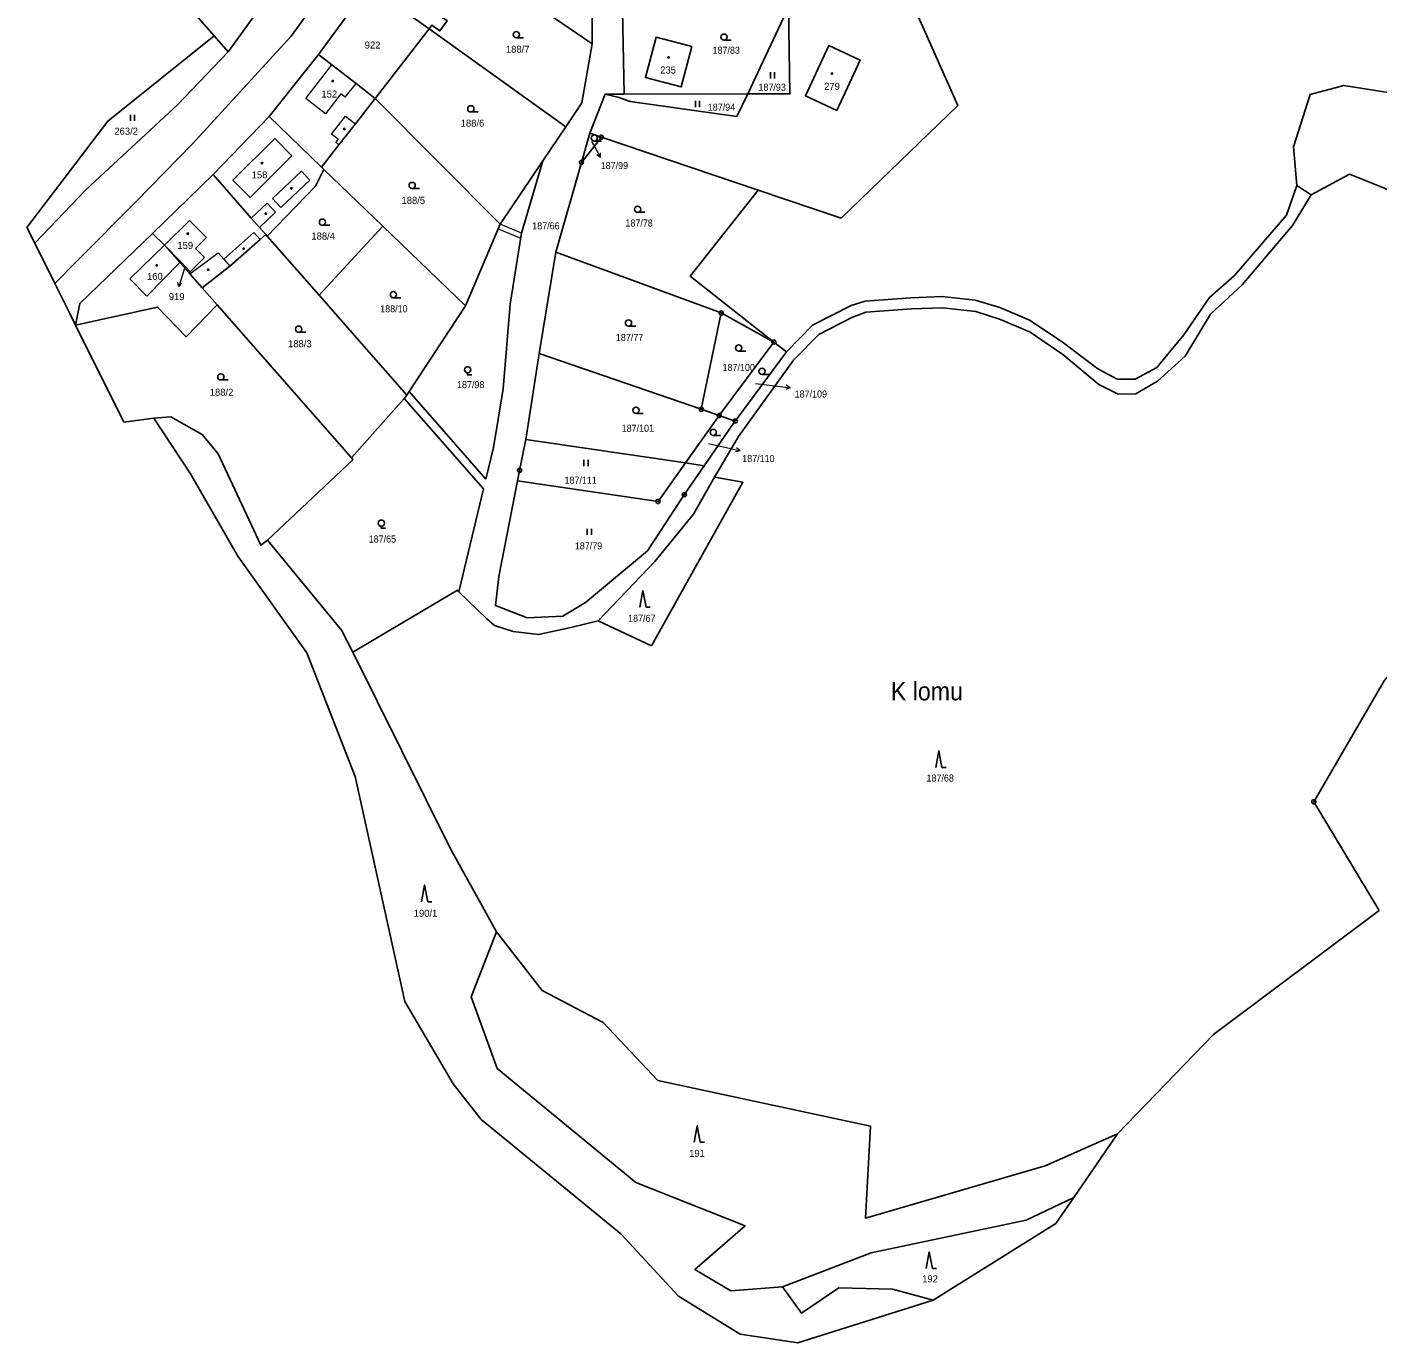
# Model space of a CAD drawing. Extents: x -754445 to -751443, y -1030748 to -1028224.
# Drawn here: x -753204.3 to -752878.6, y -1030041.6 to -1029724.1 of the extents above; entities that cross this region are included whole.
import ezdxf
from ezdxf.enums import TextEntityAlignment as Align

# ---------------------------------------------------------------- set-up
doc = ezdxf.new("R2010")
doc.units = 0
doc.header["$LTSCALE"] = 0.68
for name, color, linetype, lineweight in [('1', 7, 'Continuous', 25), ('13', 7, 'Continuous', 13), ('3', 7, 'Continuous', 25), ('4', 7, 'Continuous', 13), ('5', 7, 'Continuous', 25), ('7', 7, 'Continuous', 13), ('8', 7, 'Continuous', 25)]:
    doc.layers.add(name, color=color, linetype=linetype, lineweight=lineweight)
doc.layers.add('2', color=7, linetype='Continuous')

msp = doc.modelspace()

# ---------------------------------------------------------------- linework, layer by layer
at = {"layer": '1'}
for p, q in [((-753067.98, -1029728.16), (-753096.13, -1029708.85)), ((-753133.97, -1029730.68), (-753121.88, -1029714.12)), ((-753074.35, -1029748.12), (-753107.32, -1029724.53)), ((-753068.54, -1029749.69), (-753064.85, -1029740.24)), ((-753064.85, -1029740.24), (-753060.24, -1029740.23)), ((-753090.19, -1029771.62), (-753120.36, -1029741.3)), ((-753145.94, -1029745.69), (-753159.44, -1029759.62)), ((-753065.74, -1029750.64), (-753070.56, -1029756.75)), ((-753065.74, -1029750.64), (-753027.95, -1029763.39)), ((-753090.19, -1029771.62), (-753079.87, -1029756.31)), ((-753159.44, -1029759.62), (-753174.02, -1029773.88)), ((-753204.33, -1029772.43), (-753202.44, -1029776.23)), ((-753118.5, -1029772.12), (-753098.51, -1029791.36)), ((-753098.51, -1029791.36), (-753090.19, -1029771.62)), ((-753202.44, -1029776.23), (-753197.62, -1029785.92)), ((-753174.02, -1029773.88), (-753171.15, -1029776.66)), ((-753146.71, -1029774.13), (-753146.38, -1029774.5)), ((-753133.87, -1029788.74), (-753146.38, -1029774.5)), ((-753080.76, -1029802.85), (-753076.73, -1029778.39)), ((-753036.83, -1029793.05), (-753076.73, -1029778.39)), ((-753164.95, -1029783.09), (-753165.24, -1029783.38)), ((-753158.46, -1029791.1), (-753162.08, -1029786.99)), ((-753112.67, -1029812.9), (-753133.87, -1029788.74)), ((-753126.07, -1029828.01), (-753158.46, -1029791.1)), ((-753098.51, -1029791.36), (-753112.09, -1029812.02)), ((-753036.83, -1029793.05), (-753024.14, -1029800.06)), ((-753037.31, -1029817.79), (-753024.14, -1029800.06)), ((-753021.1, -1029802.45), (-753033.44, -1029819.12)), ((-753024.14, -1029800.06), (-753021.1, -1029802.45)), ((-753112.09, -1029812.02), (-753112.67, -1029812.9)), ((-753093.64, -1029833.17), (-753112.09, -1029812.02)), ((-753113.36, -1029813.68), (-753126.07, -1029828.01)), ((-753112.67, -1029812.9), (-753113.36, -1029813.68)), ((-753037.31, -1029817.79), (-753041.63, -1029816.3)), ((-753037.31, -1029817.79), (-753033.44, -1029819.12)), ((-753040.93, -1029829.9), (-753045.44, -1029829.23)), ((-752951.77, -1030006.47), (-752941.21, -1029991.11)), ((-753018.31, -1030041.56), (-752985.7, -1030031.26))]:
    msp.add_line(p, q, dxfattribs=at)
for points in [[(-753155.8, -1029730.07), (-753139.23, -1029707.14), (-753115.99, -1029667.05), (-753102.75, -1029643.81), (-753090.85, -1029594.8), (-753087.48, -1029564.73), (-753089.23, -1029546.78), (-753087.32, -1029532.57)], [(-753197.62, -1029785.92), (-753192.17, -1029780.43), (-753177.88, -1029766.04), (-753164.4, -1029752.26), (-753140.57, -1029726.3), (-753122.46, -1029701.36), (-753104, -1029670.46), (-753094.3, -1029652.12)], [(-753067.05, -1029673.02), (-753068.09, -1029689.28), (-753068.08, -1029699.35), (-753067.98, -1029728.16)], [(-753060.24, -1029740.23), (-753060.61, -1029720.04), (-753060.98, -1029699.54), (-753063.33, -1029699.61), (-753063.25, -1029691.47), (-753063.08, -1029680), (-753063.01, -1029674.88)], [(-753027.95, -1029763.39), (-753007.86, -1029770.18), (-752979.73, -1029743.03), (-752991.52, -1029716.57), (-752949.43, -1029707.54)], [(-753173.33, -1029710.04), (-753159.18, -1029726.19), (-753155.8, -1029730.07)], [(-753107.32, -1029724.53), (-753106.63, -1029723.59), (-753104.69, -1029725.01), (-753102.92, -1029722.59), (-753104.85, -1029721.17), (-753101.54, -1029716.65), (-753099.32, -1029713.63), (-753098.76, -1029712.87), (-753096.13, -1029708.85)], [(-753121.88, -1029714.12), (-753107.32, -1029724.53), (-753120.36, -1029741.3)], [(-753060.24, -1029740.23), (-753030.44, -1029740.19), (-753020.62, -1029719.31)], [(-753020.62, -1029719.31), (-753020.24, -1029740.17), (-753030.44, -1029740.19), (-753033.03, -1029745.69)], [(-753159.18, -1029726.19), (-753184.8, -1029746.8), (-753204.33, -1029772.43)], [(-753202.44, -1029776.23), (-753190.13, -1029763.36), (-753168.04, -1029742.83), (-753155.8, -1029730.07)], [(-753133.97, -1029730.68), (-753145.94, -1029745.69), (-753133.26, -1029757.9)], [(-753120.36, -1029741.3), (-753124.93, -1029737.73), (-753130.74, -1029733.2), (-753133.97, -1029730.68)], [(-753067.98, -1029728.16), (-753070.44, -1029742.32), (-753074.35, -1029748.12)], [(-753033.03, -1029745.69), (-753058.83, -1029742.06), (-753061.81, -1029740.96), (-753064.85, -1029740.24)], [(-752821.57, -1029768.6), (-752835.21, -1029746.28), (-752886.59, -1029738.15), (-752894.74, -1029740.31), (-752898.73, -1029753), (-752897.97, -1029762.26)], [(-753133.26, -1029757.9), (-753129.06, -1029752.49), (-753125.1, -1029747.4), (-753120.36, -1029741.3)], [(-753074.35, -1029748.12), (-753079.87, -1029756.31), (-753084.99, -1029773.81)], [(-753076.73, -1029778.39), (-753070.56, -1029756.75), (-753068.54, -1029749.69), (-753065.74, -1029750.64)], [(-753159.44, -1029759.62), (-753150.21, -1029770.15), (-753148.23, -1029772.4), (-753146.71, -1029774.13)], [(-753146.38, -1029774.5), (-753134.75, -1029762.43), (-753132.69, -1029758.45), (-753133.26, -1029757.9)], [(-753133.87, -1029788.74), (-753118.5, -1029772.12), (-753132.69, -1029758.45)], [(-752871.4, -1029765.93), (-752876.8, -1029762.95), (-752885.22, -1029759.57), (-752894.46, -1029764.58)], [(-753024.14, -1029800.06), (-753044.32, -1029784.2), (-753027.95, -1029763.39)], [(-753038.46, -1029832.64), (-753032.68, -1029822.86), (-753019.4, -1029804.4), (-753013.3, -1029798.26), (-753005.29, -1029794.12), (-753001.92, -1029792.83), (-752990.94, -1029792.09), (-752983.34, -1029791.85), (-752975.37, -1029792.7), (-752969.46, -1029794.66), (-752962.27, -1029797.65), (-752954.38, -1029803.1), (-752945.71, -1029810.31), (-752941.07, -1029812.65), (-752936.76, -1029812.6), (-752931.55, -1029809.5), (-752924.87, -1029803.5), (-752918.75, -1029793.33), (-752911.14, -1029786.28), (-752898.97, -1029771.91), (-752894.46, -1029764.58), (-752897.97, -1029762.26)], [(-752897.97, -1029762.26), (-752900.44, -1029769.47), (-752912.96, -1029784), (-752918.98, -1029789.34), (-752925.17, -1029798.31), (-752931.73, -1029806.2), (-752936.97, -1029809.01), (-752941.28, -1029809.06), (-752945.93, -1029806.54), (-752954.56, -1029800.01), (-752962.44, -1029794.75), (-752969.62, -1029791.76), (-752975.53, -1029790), (-752983.5, -1029789.06), (-752991.1, -1029789.4), (-753002.07, -1029790.23), (-753005.46, -1029791.23), (-753014.83, -1029796.03), (-753021.1, -1029802.45)], [(-753174.02, -1029773.88), (-753191.61, -1029790.74), (-753192.59, -1029796.02)], [(-753171.15, -1029776.66), (-753167.25, -1029780.7), (-753164.95, -1029783.09)], [(-753165.24, -1029783.38), (-753167.44, -1029780.88), (-753171.15, -1029776.66)], [(-753162.08, -1029786.99), (-753155.39, -1029781.74), (-753148.1, -1029775.35), (-753146.71, -1029774.13)], [(-753084.99, -1029773.81), (-753087.72, -1029790.91), (-753089.46, -1029811.38), (-753091.8, -1029825.52), (-753093.64, -1029833.17)], [(-753165.24, -1029783.38), (-753165.06, -1029783.59), (-753162.08, -1029786.99)], [(-753197.62, -1029785.92), (-753194, -1029793.19), (-753192.59, -1029796.02)], [(-753192.59, -1029796.02), (-753172.86, -1029791.63), (-753165.89, -1029798.8), (-753158.46, -1029791.1)], [(-753080.76, -1029802.85), (-753041.63, -1029816.3), (-753036.83, -1029793.05)], [(-753192.59, -1029796.02), (-753180.96, -1029819.39), (-753173.72, -1029818.43)], [(-753085.95, -1029833.53), (-753085.46, -1029831.03), (-753083.99, -1029823.54), (-753080.76, -1029802.85)], [(-753100.13, -1029860.36), (-753094.21, -1029835.5), (-753113.36, -1029813.68)], [(-753173.72, -1029818.43), (-753169.64, -1029818.1), (-753162.08, -1029822.36), (-753158.18, -1029827.05), (-753147.91, -1029849.09), (-753146.33, -1029847.85)], [(-753173.72, -1029818.43), (-753164.91, -1029831.89), (-753153.46, -1029851.72)], [(-753083.99, -1029823.54), (-753045.44, -1029829.23), (-753037.31, -1029817.79)], [(-753033.44, -1029819.12), (-753034.38, -1029820.39), (-753040.93, -1029829.9)], [(-753126.07, -1029828.01), (-753125.68, -1029828.46), (-753146.33, -1029847.85)], [(-752878.06, -1029937.24), (-752893.85, -1029910.98), (-752876.9, -1029881.79), (-752854.13, -1029855.53), (-752840.44, -1029842.55), (-752829.34, -1029828.87)], [(-753040.93, -1029829.9), (-753045.74, -1029836.9), (-753046.24, -1029837.63), (-753054.62, -1029850.43), (-753069.55, -1029862.87), (-753075.05, -1029866.17), (-753083.66, -1029866.63), (-753091.32, -1029863.63), (-753090.51, -1029856.65), (-753085.95, -1029833.53)], [(-753045.44, -1029829.23), (-753052.06, -1029838.53), (-753085.95, -1029833.53)], [(-753066.49, -1029867.32), (-753052.87, -1029852.98), (-753043.54, -1029841.59), (-753038.46, -1029832.64)], [(-753066.49, -1029867.32), (-753053.69, -1029873.33), (-753031.6, -1029833.88), (-753038.46, -1029832.64)], [(-753146.33, -1029847.85), (-753128.41, -1029869.56), (-753125.74, -1029874.9)], [(-753153.46, -1029851.72), (-753136.8, -1029875.02), (-753125.17, -1029904.88), (-753113.17, -1029959.19)], [(-753125.74, -1029874.9), (-753100.48, -1029859.97), (-753100.13, -1029860.36)], [(-753100.13, -1029860.36), (-753093.38, -1029866.87), (-753091.5, -1029868.49), (-753087.01, -1029869.9), (-753080.89, -1029870.66), (-753073.13, -1029868.97), (-753066.49, -1029867.32)], [(-753125.74, -1029874.9), (-753102.14, -1029922.35), (-753091.08, -1029942.34)], [(-752941.21, -1029991.11), (-752918.04, -1029967.16), (-752878.06, -1029937.24)], [(-753022.06, -1030028), (-753034.48, -1030028.99), (-753043.2, -1030023.85), (-753031.08, -1030013.28), (-753057.45, -1030002.85), (-753090.9, -1029975.31), (-753097.15, -1029958.06), (-753091.08, -1029942.34)], [(-753091.08, -1029942.34), (-753080, -1029956.49), (-753065.31, -1029964.22), (-753052.13, -1029978.19), (-753000.79, -1029989.23), (-753002.02, -1030011.43), (-752958.68, -1029998.8), (-752941.21, -1029991.11)], [(-753113.17, -1029959.19), (-753101.54, -1029979), (-753094.73, -1029987.61), (-753061.01, -1030015.19)], [(-753022.06, -1030028), (-753000.67, -1030019.83), (-752963.22, -1030011.91), (-752951.77, -1030006.47)], [(-752985.7, -1030031.26), (-752956.07, -1030012.72), (-752951.77, -1030006.47)], [(-753061.01, -1030015.19), (-753047.16, -1030030.26), (-753032.28, -1030039.4), (-753018.31, -1030041.56)], [(-752985.7, -1030031.26), (-752995.51, -1030028.58), (-753008.46, -1030028.27), (-753017.42, -1030034.39), (-753022.06, -1030028)]]:
    msp.add_lwpolyline(points, dxfattribs=at)
for points in [[(-753052.55, -1029726.51), (-753055.12, -1029736.24), (-753046.5, -1029738.52), (-753043.93, -1029728.79)], [(-753008.95, -1029744.18), (-753016.53, -1029740.64), (-753010.87, -1029728.52), (-753003.29, -1029732.09)]]:
    msp.add_lwpolyline(points, close=True, dxfattribs=at)
at = {"layer": '13'}
msp.add_lwpolyline([(-753090.19, -1029771.62), (-753090.65, -1029772.73), (-753085.19, -1029775.03), (-753084.99, -1029773.81)], close=True, dxfattribs=at)
at = {"layer": '3'}
for p, q in [((-753086.253, -1029726.67), (-753084.503, -1029726.67)), ((-753036.163, -1029727.25), (-753034.413, -1029727.25)), ((-753024.951, -1029736.46), (-753024.951, -1029734.96)), ((-753023.95, -1029736.46), (-753023.95, -1029734.96)), ((-753043.051, -1029743.38), (-753043.051, -1029741.88)), ((-753042.05, -1029743.38), (-753042.05, -1029741.88)), ((-753179.371, -1029746.73), (-753179.371, -1029745.23)), ((-753178.37, -1029746.73), (-753178.37, -1029745.23)), ((-753097.243, -1029744.55), (-753095.493, -1029744.55)), ((-753067.473, -1029751.61), (-753065.723, -1029751.61)), ((-753111.393, -1029763.04), (-753109.643, -1029763.04)), ((-753056.993, -1029768.77), (-753055.243, -1029768.77)), ((-753133.043, -1029771.89), (-753131.293, -1029771.89)), ((-753115.913, -1029789.41), (-753114.163, -1029789.41)), ((-753059.193, -1029796.23), (-753057.443, -1029796.23)), ((-753138.803, -1029797.71), (-753137.053, -1029797.71)), ((-753032.623, -1029802.23), (-753030.873, -1029802.23)), ((-753157.563, -1029809.22), (-753155.813, -1029809.22)), ((-753026.983, -1029807.88), (-753025.233, -1029807.88)), ((-753057.383, -1029817.27), (-753055.633, -1029817.27)), ((-753038.763, -1029822.63), (-753037.013, -1029822.63)), ((-753069.961, -1029830), (-753069.961, -1029828.5)), ((-753068.96, -1029830), (-753068.96, -1029828.5)), ((-753069.161, -1029846.61), (-753069.161, -1029845.11)), ((-753068.16, -1029846.61), (-753068.16, -1029845.11)), ((-753054.97, -1029864.04), (-753053.974, -1029864.04)), ((-752983.56, -1029902.68), (-752982.564, -1029902.68)), ((-753107.65, -1029935.1), (-753106.654, -1029935.1)), ((-753041.87, -1029993.13), (-753040.874, -1029993.13)), ((-752985.87, -1030023.59), (-752984.874, -1030023.59))]:
    msp.add_line(p, q, dxfattribs=at)
for points in [[(-753098.03, -1029807.512), (-753098.03, -1029808.01), (-753097.029, -1029808.01)], [(-753118.85, -1029844.512), (-753118.85, -1029845.01), (-753117.849, -1029845.01)], [(-753054.97, -1029864.04), (-753055.72, -1029860.04), (-753056.47, -1029864.04)], [(-752983.56, -1029902.68), (-752984.31, -1029898.68), (-752985.06, -1029902.68)], [(-753107.65, -1029935.1), (-753108.4, -1029931.1), (-753109.15, -1029935.1)], [(-753041.87, -1029993.13), (-753042.62, -1029989.13), (-753043.37, -1029993.13)], [(-752985.87, -1030023.59), (-752986.62, -1030019.59), (-752987.37, -1030023.59)]]:
    msp.add_lwpolyline(points, dxfattribs=at)
for centre in [(-753086.2529, -1029725.9198), (-753036.1629, -1029726.4998), (-753097.2429, -1029743.7998), (-753067.4729, -1029750.8598), (-753111.3929, -1029762.2898), (-753133.0429, -1029771.1398), (-753056.9929, -1029768.0198), (-753115.9129, -1029788.6598), (-753138.8029, -1029796.9598), (-753059.1929, -1029795.4798), (-753032.6229, -1029801.4798), (-753098.0293, -1029806.7609), (-753157.5629, -1029808.4698), (-753026.9829, -1029807.1298), (-753057.3829, -1029816.5198), (-753038.7629, -1029821.8798), (-753118.8493, -1029843.7609)]:
    msp.add_circle(centre, 0.75, dxfattribs=at)
at = {"layer": '4'}
for p, q in [((-753137.03, -1029741.31), (-753130.74, -1029733.2)), ((-753127.56, -1029741), (-753124.93, -1029737.73)), ((-753128.58, -1029740.21), (-753132.29, -1029744.99)), ((-753127.56, -1029741), (-753128.58, -1029740.21)), ((-753132.29, -1029744.99), (-753137.03, -1029741.31)), ((-753130.84, -1029749.9), (-753127.47, -1029745.56)), ((-753127.47, -1029745.56), (-753125.1, -1029747.4)), ((-753129.26, -1029751.13), (-753130.84, -1029749.9)), ((-753144.57, -1029750.97), (-753154.66, -1029761.03)), ((-753144.57, -1029750.97), (-753140.41, -1029755.14)), ((-753129.26, -1029751.13), (-753129.85, -1029751.88)), ((-753129.85, -1029751.88), (-753129.06, -1029752.49)), ((-753140.41, -1029755.14), (-753150.5, -1029765.2)), ((-753145.11, -1029765.4), (-753138.09, -1029758.85)), ((-753138.09, -1029758.85), (-753136.05, -1029761.04)), ((-753150.5, -1029765.2), (-753154.66, -1029761.03)), ((-753143.07, -1029767.59), (-753136.05, -1029761.04)), ((-753150.21, -1029770.15), (-753146.39, -1029766.58)), ((-753146.39, -1029766.58), (-753144.34, -1029768.77)), ((-753145.11, -1029765.4), (-753143.07, -1029767.59)), ((-753148.23, -1029772.4), (-753144.34, -1029768.77)), ((-753171.15, -1029776.66), (-753165.15, -1029770.73)), ((-753165.15, -1029770.73), (-753161.05, -1029774.84)), ((-753156.87, -1029780.05), (-753149.58, -1029773.66)), ((-753148.1, -1029775.35), (-753149.58, -1029773.66)), ((-753171.15, -1029776.66), (-753179.51, -1029784.78)), ((-753165.06, -1029783.59), (-753158.22, -1029778.51)), ((-753158.22, -1029778.51), (-753156.87, -1029780.05)), ((-753156.87, -1029780.05), (-753155.39, -1029781.74)), ((-753175.43, -1029788.98), (-753167.44, -1029780.88)), ((-753175.43, -1029788.98), (-753179.51, -1029784.78))]:
    msp.add_line(p, q, dxfattribs=at)
msp.add_lwpolyline([(-753164.95, -1029783.09), (-753161.52, -1029779.67), (-753163.67, -1029777.46), (-753161.05, -1029774.84)], dxfattribs=at)
at = {"layer": '5'}
for centre in [(-753049.5268, -1029731.3992), (-753130.5568, -1029737.1192), (-753010.1068, -1029735.2992), (-753127.7768, -1029748.6592), (-753147.6168, -1029756.8992), (-753140.5268, -1029762.9792), (-753146.7168, -1029769.0692), (-753165.5268, -1029773.9292), (-753152.0368, -1029777.5592), (-753173.0268, -1029781.5792), (-753160.5868, -1029782.6292)]:
    msp.add_circle(centre, 0.175, dxfattribs=at)
at = {"layer": '7'}
for p, q in [((-753065.92, -1029755.519), (-753065.987, -1029754.401)), ((-753167.727, -1029786.7), (-753166.956, -1029785.889)), ((-753020.211, -1029811.116), (-753021.144, -1029810.497)), ((-753032.276, -1029826.295), (-753033.139, -1029825.582))]:
    msp.add_line(p, q, dxfattribs=at)
for points in [[(-753068.11, -1029751.72), (-753067.42, -1029752.92), (-753065.92, -1029755.519), (-753066.854, -1029754.902)], [(-753166.26, -1029781.93), (-753166.85, -1029783.83), (-753167.727, -1029786.7), (-753167.913, -1029785.596)], [(-753028.54, -1029810.07), (-753023.19, -1029810.75), (-753020.211, -1029811.116), (-753021.266, -1029811.491)], [(-753039.9, -1029824.54), (-753035.2, -1029825.62), (-753032.276, -1029826.295), (-753033.364, -1029826.558)]]:
    msp.add_lwpolyline(points, dxfattribs=at)
at = {"layer": '8'}
for centre, radius in [((-753065.74, -1029750.6399), 0.5), ((-753065.74, -1029750.6399), 0.0303), ((-753070.56, -1029756.7499), 0.5), ((-753070.56, -1029756.7499), 0.0303), ((-753036.83, -1029793.0499), 0.5), ((-753036.83, -1029793.0499), 0.0303), ((-753024.14, -1029800.0599), 0.5), ((-753024.14, -1029800.0599), 0.0303), ((-753041.63, -1029816.2999), 0.5), ((-753041.63, -1029816.2999), 0.0303), ((-753037.31, -1029817.7899), 0.5), ((-753037.31, -1029817.7899), 0.0303), ((-753033.44, -1029819.1199), 0.5), ((-753033.44, -1029819.1199), 0.0303), ((-753085.46, -1029831.0299), 0.5), ((-753085.46, -1029831.0299), 0.0303), ((-753052.06, -1029838.5299), 0.5), ((-753052.06, -1029838.5299), 0.0303), ((-753045.74, -1029836.8999), 0.5), ((-753045.74, -1029836.8999), 0.0303), ((-752893.85, -1029910.9799), 0.5), ((-752893.85, -1029910.9799), 0.0303)]:
    msp.add_circle(centre, radius, dxfattribs=at)

# ---------------------------------------------------------------- texts
at = {"layer": '2'}
for s, p in [('922', (-753120.949, -1029729.27)), ('188/7', (-753085.93, -1029730.28)), ('235', (-753049.659, -1029735.29)), ('279', (-753010.099, -1029739.23)), ('152', (-753131.399, -1029741.09)), ('188/6', (-753096.84, -1029748.11)), ('263/2', (-753180.4, -1029750.04)), ('158', (-753148.219, -1029760.57)), ('188/5', (-753111.12, -1029766.73)), ('188/4', (-753132.87, -1029775.35)), ('159', (-753166.149, -1029777.6)), ('160', (-753173.479, -1029785.07)), ('919', (-753168.219, -1029789.96)), ('188/3', (-753138.5, -1029801.32)), ('188/2', (-753157.39, -1029813.03)), ('190/1', (-753108.17, -1029938.73)), ('191', (-753042.669, -1029996.66)), ('192', (-752986.449, -1030026.94))]:
    msp.add_text(s, height=1.7, dxfattribs=at).set_placement(p, align=Align.CENTER)
at = {"layer": '2', "width": 0.95}
for s, p in [('187/83', (-753035.629, -1029730.53)), ('187/93', (-753024.539, -1029739.44)), ('187/94', (-753036.769, -1029744.26)), ('187/78', (-753056.639, -1029772.2)), ('187/66', (-753079.129, -1029772.89)), ('188/10', (-753115.809, -1029792.89)), ('187/77', (-753058.939, -1029799.81)), ('187/98', (-753097.269, -1029811.19)), ('187/109', (-753015.21, -1029813.46)), ('187/110', (-753027.86, -1029829.01)), ('187/65', (-753118.589, -1029848.44)), ('187/79', (-753068.849, -1029850.09)), ('187/67', (-753055.999, -1029867.55)), ('187/68', (-752983.999, -1029906.11))]:
    msp.add_text(s, height=1.7, dxfattribs=at).set_placement(p, align=Align.CENTER)
for s, p in [('187/99', (-753065.91, -1029758.343)), ('187/100', (-753036.51, -1029807.04)), ('187/101', (-753060.85, -1029821.72)), ('187/111', (-753074.64, -1029834.26))]:
    msp.add_text(s, height=1.7, dxfattribs=at).set_placement(p)
at = {"layer": '7', "width": 0.95}
msp.add_text('K lomu', height=4.4, dxfattribs=at).set_placement((-752987.21, -1029886.518), align=Align.CENTER)

doc.saveas('drawing.dxf')
